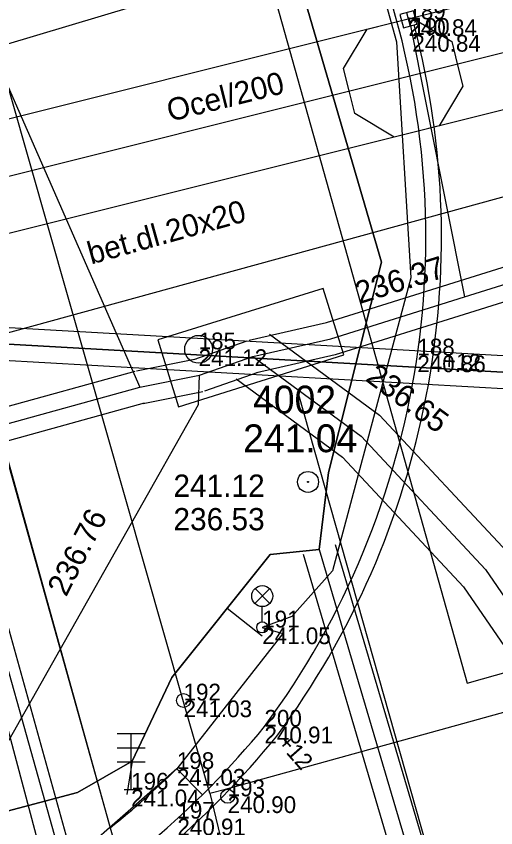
# Model space of a CAD drawing. Extents: x -599432 to -598680, y -1159407 to -1158632.
# Drawn here: x -599037.98 to -599029.38, y -1158897.84 to -1158883.28 of the extents above; entities that cross this region are included whole.
import ezdxf

# ---------------------------------------------------------------- set-up
doc = ezdxf.new("R2010")
doc.units = 0
for name, color, linetype in [('0001 VY - Body PBP', 7, 'Continuous'), ('0002 VY - Body PBP - čísla', 7, 'Continuous'), ('0003 VY - Body PBP - výšky', 7, 'Continuous'), ('0004 VY - Body podrobné', 7, 'Continuous'), ('0005 VY - Body podrobné - čísla', 7, 'Continuous'), ('0006 VY - Body podrobné - výšky', 7, 'Continuous'), ('0027 ZA - Silnice_cesta zpevněná', 7, 'Continuous'), ('0031 ZA - Ostatní rozhraní', 7, 'Continuous'), ('0032 TE - Popis povrchu', 7, 'Continuous'), ('0057 ZA - Doprava - BKOM buňky', 7, 'Continuous'), ('0073 TE - Výška obrubníků a zdí', 7, 'Continuous'), ('0075 ZA - BVK - kanalizace - buňky', 7, 'Continuous'), ('0080 ZA - BVK - vodovod - buňky', 7, 'Continuous'), ('0105 ZA - TSB - VO - buňky', 7, 'Continuous'), ('0201 PV - BVK - kanalizace - popis', 7, 'Continuous'), ('0203 PV - BVK - kanalizace - dešťová přípojka', 7, 'Continuous'), ('0206 PV - BVK - kanalizace - jednotná', 7, 'Continuous'), ('0209 PV - BVK - kanalizace - obvod šachty', 7, 'Continuous'), ('0211 PV - BVK - kanalizace - jednotná okraj', 7, 'Continuous'), ('0214 PV - BVK - vodovod - pitná', 7, 'Continuous'), ('0264 PV - TB - parovod mimo provoz', 7, 'Continuous'), ('0301 PV - RWE - popis', 7, 'Continuous'), ('0302 PV - RWE - NTL', 7, 'Continuous'), ('0308 PV - RWE - ochranné pásmo', 7, 'Continuous'), ('0359 PV - EON - sdělovací kabely', 7, 'Continuous'), ('0368 PV - EON - sdělovací chránička', 7, 'Continuous'), ('0407 PV - TSB - kabelové vedení přibližný zákres', 7, 'Continuous'), ('0454 PV - O2 - kabel zaměřený', 7, 'Continuous'), ('0455 PV - O2 - kabel nezaměřený', 7, 'Continuous'), ('0530 PV - T-mobile - optické kabely', 7, 'Continuous'), ('0652 PV - BKOM - kabely bez rozlišení', 7, 'Continuous'), ('0653 PV - BKOM - chranička', 7, 'Continuous'), ('0703 PV - DIAL TELECOM optický kabel', 7, 'Continuous')]:
    doc.layers.add(name, color=color, linetype=linetype)

msp = doc.modelspace()

# ---------------------------------------------------------------- linework, layer by layer
at = {"layer": '0001 VY - Body PBP'}
for radius in [0.188, 0.00896]:
    msp.add_circle((-599032.75, -1158891.64), radius, dxfattribs=at)
at = {"layer": '0004 VY - Body podrobné'}
for p, q in [((-599030.95, -1158883.34), (-599030.95, -1158883.34)), ((-599030.88, -1158883.62), (-599030.88, -1158883.62)), ((-599034.71, -1158889.26), (-599034.71, -1158889.26)), ((-599030.79, -1158889.37), (-599030.79, -1158889.37)), ((-599033.57, -1158894.25), (-599033.57, -1158894.25)), ((-599034.98, -1158895.56), (-599034.98, -1158895.56)), ((-599033.53, -1158896.03), (-599033.53, -1158896.03)), ((-599035.1, -1158896.79), (-599035.1, -1158896.79)), ((-599035.92, -1158897.16), (-599035.92, -1158897.16)), ((-599034.19, -1158897.28), (-599034.19, -1158897.28)), ((-599035.09, -1158897.68), (-599035.09, -1158897.68))]:
    msp.add_line(p, q, dxfattribs=at)
at = {"layer": '0027 ZA - Silnice_cesta zpevněná'}
for centre, radius, start, end in [((-599045.404, -1158887.251), 14.766, 323.5232, 19.0984), ((-599045.614, -1158886.167), 15.598, 299.5987, 320.7801)]:
    msp.add_arc(centre, radius, start, end, dxfattribs=at)
at = {"layer": '0031 ZA - Ostatní rozhraní'}
for p, q in [((-599041.68, -1158878.521), (-599036.294, -1158897.844)), ((-599041.14, -1158883.437), (-599036.98, -1158898.36)), ((-599034.641, -1158897.253), (-599035.104, -1158896.786))]:
    msp.add_line(p, q, dxfattribs=at)
for centre, radius, start, end in [((-599045.404, -1158887.251), 15.046, 323.4977, 14.6672), ((-599045.614, -1158886.167), 15.878, 299.5786, 320.8043), ((-599045.614, -1158886.167), 14.94, 308.5987, 314.7062)]:
    msp.add_arc(centre, radius, start, end, dxfattribs=at)
at = {"layer": '0057 ZA - Doprava - BKOM buňky'}
for p, q in [((-599035.67, -1158896.16), (-599036.17, -1158896.16)), ((-599035.92, -1158897.16), (-599035.92, -1158896.16)), ((-599036.17, -1158896.41), (-599035.67, -1158896.41)), ((-599036.17, -1158896.66), (-599035.67, -1158896.66)), ((-599036.045, -1158897.16), (-599035.795, -1158897.16))]:
    msp.add_line(p, q, dxfattribs=at)
at = {"layer": '0075 ZA - BVK - kanalizace - buňky'}
msp.add_line((-599030.983, -1158883.219), (-599030.917, -1158883.461), dxfattribs=at)
msp.add_lwpolyline([(-599031.103, -1158883.252), (-599031.038, -1158883.493), (-599030.797, -1158883.428), (-599030.862, -1158883.187)], close=True, dxfattribs=at)
msp.add_circle((-599034.71, -1158889.26), 0.25, dxfattribs=at)
at = {"layer": '0080 ZA - BVK - vodovod - buňky'}
for centre in [(-599034.98, -1158895.56), (-599034.19, -1158897.28)]:
    msp.add_circle(centre, 0.125, dxfattribs=at)
at = {"layer": '0105 ZA - TSB - VO - buňky'}
for p, q in [((-599033.434, -1158893.818), (-599033.698, -1158893.553)), ((-599033.702, -1158893.819), (-599033.438, -1158893.555)), ((-599033.57, -1158894.15), (-599033.57, -1158893.875))]:
    msp.add_line(p, q, dxfattribs=at)
for centre, radius in [((-599033.57, -1158893.688), 0.188), ((-599033.57, -1158894.25), 0.1)]:
    msp.add_circle(centre, radius, dxfattribs=at)
at = {"layer": '0203 PV - BVK - kanalizace - dešťová přípojka'}
msp.add_line((-599030.942, -1158883.305), (-599029.946, -1158888.32), dxfattribs=at)
msp.add_line((-599030.942, -1158883.305), (-599029.946, -1158888.32), dxfattribs=at)
at = {"layer": '0206 PV - BVK - kanalizace - jednotná'}
for p, q in [((-599041.22, -1158877.49), (-599035.766, -1158889.94)), ((-599041.22, -1158877.49), (-599035.766, -1158889.94)), ((-599034.697, -1158889.724), (-599033.74, -1158889.39)), ((-599035.766, -1158889.94), (-599034.697, -1158889.724)), ((-599034.71, -1158890.253), (-599034.697, -1158889.724)), ((-599034.71, -1158890.253), (-599034.697, -1158889.724)), ((-599091.321, -1158905.303), (-599035.766, -1158889.94)), ((-599055.379, -1158926.835), (-599034.71, -1158890.253)), ((-599055.379, -1158926.835), (-599034.71, -1158890.253))]:
    msp.add_line(p, q, dxfattribs=at)
for points in [[(-599033.74, -1158889.39), (-599032.341, -1158889.07), (-599029.946, -1158888.32), (-599018.079, -1158884.603)], [(-599033.74, -1158889.39), (-599031.8, -1158890.82), (-599029.57, -1158893.21), (-599027.06, -1158896.87), (-599025.46, -1158900.47), (-599024.64, -1158903.44), (-599009.567, -1158957.636)]]:
    msp.add_lwpolyline(points, dxfattribs=at)
at = {"layer": '0209 PV - BVK - kanalizace - obvod šachty'}
msp.add_lwpolyline([(-599035.44, -1158889.09), (-599035.07, -1158890.29), (-599032.11, -1158889.36), (-599032.48, -1158888.17)], close=True, dxfattribs=at)
at = {"layer": '0211 PV - BVK - kanalizace - jednotná okraj'}
for p, q in [((-599034.796, -1158889.441), (-599033.839, -1158889.107)), ((-599035.825, -1158889.646), (-599034.756, -1158889.43)), ((-599091.401, -1158905.014), (-599035.846, -1158889.651)), ((-599034.598, -1158890.007), (-599033.641, -1158889.673)), ((-599035.707, -1158890.234), (-599034.638, -1158890.018)), ((-599035.686, -1158890.229), (-599091.242, -1158905.592))]:
    msp.add_line(p, q, dxfattribs=at)
for points in [[(-599033.807, -1158889.098), (-599032.419, -1158888.78), (-599030.036, -1158888.034), (-599018.169, -1158884.317)], [(-599017.989, -1158884.889), (-599029.856, -1158888.606), (-599032.263, -1158889.36), (-599033.673, -1158889.682)], [(-599033.443, -1158888.988), (-599031.466, -1158890.445), (-599029.179, -1158892.896), (-599026.622, -1158896.625), (-599024.988, -1158900.301), (-599024.158, -1158903.306), (-599009.085, -1158957.502)], [(-599034.037, -1158889.792), (-599032.134, -1158891.195), (-599029.961, -1158893.524), (-599027.498, -1158897.115), (-599025.932, -1158900.639), (-599025.122, -1158903.574), (-599010.049, -1158957.77)]]:
    msp.add_lwpolyline(points, dxfattribs=at)
at = {"layer": '0214 PV - BVK - vodovod - pitná'}
for q in [(-599034.98, -1158895.587), (-599034.23, -1158897.15)]:
    msp.add_line((-599034.512, -1158897.222), q, dxfattribs=at)
for points in [[(-599034.98, -1158895.587), (-599043.597, -1158865.343), (-599050.485, -1158841.158), (-599054.704, -1158825.464)], [(-599034.23, -1158897.15), (-599025.055, -1158894.612), (-599019.244, -1158893.004), (-599016.56, -1158892.26), (-599016.08, -1158892.128)], [(-599034.512, -1158897.222), (-599034.25, -1158898.295), (-599033.898, -1158899.704)]]:
    msp.add_lwpolyline(points, dxfattribs=at)
at = {"layer": '0264 PV - TB - parovod mimo provoz'}
for p, q in [((-599015.807, -1158882.836), (-599046.634, -1158891.306)), ((-599017.96, -1158942.926), (-599032.913, -1158890.076))]:
    msp.add_line(p, q, dxfattribs=at)
at = {"layer": '0302 PV - RWE - NTL'}
for points in [[(-599031.044, -1158884.383), (-598999.16, -1158876.4), (-598995.29, -1158875.42), (-598995.15, -1158875.39), (-598995.04, -1158875.36)], [(-599039.1, -1158886.4), (-599031.044, -1158884.383)], [(-599039.81, -1158889.02), (-599019.564, -1158961.355)]]:
    msp.add_lwpolyline(points, dxfattribs=at)
at = {"layer": '0308 PV - RWE - ochranné pásmo'}
for points in [[(-599031.689, -1158883.514), (-599031.287, -1158883.413), (-598999.404, -1158875.43), (-598995.518, -1158874.446), (-598995.387, -1158874.418), (-598995.303, -1158874.395), (-598994.903, -1158874.286), (-598994.184, -1158874.697), (-598994.075, -1158875.097), (-598993.966, -1158875.497), (-598994.377, -1158876.216), (-598994.777, -1158876.325), (-598994.913, -1158876.362), (-598995.062, -1158876.394), (-598998.916, -1158877.37), (-599030.801, -1158885.353), (-599031.203, -1158885.454), (-599031.913, -1158885.028), (-599032.014, -1158884.626), (-599032.115, -1158884.224)], [(-599039.745, -1158885.531), (-599039.343, -1158885.43), (-599031.287, -1158883.413), (-599030.885, -1158883.312), (-599030.175, -1158883.738), (-599030.074, -1158884.14), (-599029.973, -1158884.542), (-599030.399, -1158885.252), (-599030.801, -1158885.353), (-599038.857, -1158887.37), (-599039.259, -1158887.471), (-599039.969, -1158887.045), (-599040.07, -1158886.643), (-599040.171, -1158886.241)], [(-599018.602, -1158961.079), (-599020.526, -1158961.63), (-599040.773, -1158889.29), (-599040.885, -1158888.891), (-599040.479, -1158888.169), (-599040.08, -1158888.057), (-599039.681, -1158887.945), (-599038.959, -1158888.351), (-599038.847, -1158888.75)]]:
    msp.add_lwpolyline(points, close=True, dxfattribs=at)
at = {"layer": '0359 PV - EON - sdělovací kabely'}
msp.add_lwpolyline([(-599153, -1158925.67), (-599136.91, -1158920.86), (-599119.51, -1158916.31), (-599104.33, -1158911.91), (-599088.3, -1158908.08), (-599074.72, -1158903.34), (-599063.86, -1158900.66), (-599061.95, -1158898.88), (-599061.24, -1158895.32), (-599061.55, -1158893.87), (-599062.09, -1158890.79), (-599061.3, -1158889.79), (-599054.31, -1158887.73), (-599051.84, -1158888.39), (-598992.76, -1158891.74), (-598991.64, -1158891.24), (-598990.73, -1158890.27)], dxfattribs=at)
msp.add_lwpolyline([(-599153, -1158925.67), (-599136.91, -1158920.86), (-599119.51, -1158916.31), (-599104.33, -1158911.91), (-599088.3, -1158908.08), (-599074.72, -1158903.34), (-599063.86, -1158900.66), (-599061.95, -1158898.88), (-599061.24, -1158895.32), (-599061.55, -1158893.87), (-599062.09, -1158890.79), (-599061.3, -1158889.79), (-599054.31, -1158887.73), (-599051.84, -1158888.39), (-598992.76, -1158891.74), (-598991.64, -1158891.24), (-598990.73, -1158890.27)], dxfattribs=at)
at = {"layer": '0368 PV - EON - sdělovací chránička'}
for p, q in [((-599051.823, -1158888.09), (-598992.743, -1158891.44)), ((-598992.777, -1158892.04), (-599051.857, -1158888.69))]:
    msp.add_line(p, q, dxfattribs=at)
at = {"layer": '0407 PV - TSB - kabelové vedení přibližný zákres'}
for p, q in [((-599034.231, -1158872.76), (-599031.163, -1158883.745)), ((-599031.163, -1158883.745), (-599030.908, -1158887.981)), ((-599030.908, -1158887.981), (-599032.311, -1158893.237)), ((-599032.311, -1158893.237), (-599033.038, -1158894.054)), ((-599033.038, -1158894.054), (-599033.57, -1158894.25)), ((-599033.57, -1158894.25), (-599033.204, -1158894.36)), ((-599033.204, -1158894.36), (-599035.104, -1158896.786)), ((-599035.104, -1158896.786), (-599037.938, -1158899.272))]:
    msp.add_line(p, q, dxfattribs=at)
at = {"layer": '0454 PV - O2 - kabel zaměřený'}
msp.add_lwpolyline([(-599033.5, -1158882.39), (-599029.9, -1158895.25), (-599027.59, -1158894.6), (-599014.08, -1158890.98), (-599009.96, -1158889.87)], dxfattribs=at)
at = {"layer": '0455 PV - O2 - kabel nezaměřený'}
msp.add_lwpolyline([(-599033.5, -1158882.39), (-599041.16, -1158884.69), (-599029.5, -1158928.59)], dxfattribs=at)
at = {"layer": '0530 PV - T-mobile - optické kabely'}
msp.add_lwpolyline([(-598992.76, -1158891.739), (-599051.839, -1158888.389)], dxfattribs=at)
at = {"layer": '0652 PV - BKOM - kabely bez rozlišení'}
for p, q in [((-599034.196, -1158893.902), (-599033.57, -1158894.4)), ((-599035.9, -1158896.65), (-599036, -1158897.25))]:
    msp.add_line(p, q, dxfattribs=at)
for points in [[(-599069.54, -1158906.27), (-599056.01, -1158902.46), (-599042.94, -1158898.82), (-599036.88, -1158897.21), (-599035.9, -1158896.65), (-599035.19, -1158895.15), (-599033.43, -1158892.94), (-599032.55, -1158892.85), (-599032.38, -1158891.47), (-599031.43, -1158887.7), (-599033.39, -1158880.98), (-599034.34, -1158877.53), (-599034.11, -1158876.42), (-599020.38, -1158872.59), (-599019.95, -1158872.38), (-599019.48, -1158873.04), (-599018.91, -1158874.17), (-599016.73, -1158875.93), (-599015.62, -1158876.75), (-599013.57, -1158877.37), (-599011.16, -1158877.03), (-599007.55, -1158875.71), (-599006.793, -1158874.464)], [(-599034.11, -1158876.42), (-599034.34, -1158877.53), (-599033.39, -1158880.98), (-599031.43, -1158887.7), (-599032.38, -1158891.47), (-599032.55, -1158892.85), (-599033.43, -1158892.94), (-599035.19, -1158895.15), (-599035.9, -1158896.65), (-599036.88, -1158897.21), (-599042.94, -1158898.82), (-599056.01, -1158902.46), (-599055.88, -1158902.71)], [(-599032.55, -1158892.85), (-599025.77, -1158915.82), (-599025.82, -1158914.68), (-599026.87, -1158913.05), (-599029.47, -1158911.41), (-599032.14, -1158911.02), (-599033.01, -1158911.65), (-599035.81, -1158912.5), (-599040.07, -1158913.21)]]:
    msp.add_lwpolyline(points, dxfattribs=at)
at = {"layer": '0653 PV - BKOM - chranička'}
for p, q in [((-599032.262, -1158892.765), (-599025.482, -1158915.735)), ((-599032.838, -1158892.935), (-599026.058, -1158915.905))]:
    msp.add_line(p, q, dxfattribs=at)
at = {"layer": '0703 PV - DIAL TELECOM optický kabel'}
for points in [[(-598991.64, -1158891.24), (-598992.76, -1158891.74), (-599051.84, -1158888.39), (-599054.31, -1158887.73), (-599061.3, -1158889.79), (-599062.09, -1158890.79), (-599061.55, -1158893.87)], [(-598992.76, -1158891.74), (-599051.84, -1158888.39)]]:
    msp.add_lwpolyline(points, dxfattribs=at)

# ---------------------------------------------------------------- texts
at = {"layer": '0002 VY - Body PBP - čísla'}
msp.add_text('4002', height=0.5, dxfattribs=at).set_placement((-599033.734, -1158890.413))
at = {"layer": '0003 VY - Body PBP - výšky'}
msp.add_text('241.04', height=0.5, dxfattribs=at).set_placement((-599033.912, -1158891.107))
at = {"layer": '0005 VY - Body podrobné - čísla'}
for s, p in [('189', (-599030.95, -1158883.34)), ('190', (-599030.88, -1158883.62)), ('185', (-599034.71, -1158889.26)), ('188', (-599030.79, -1158889.37)), ('191', (-599033.57, -1158894.25)), ('192', (-599034.98, -1158895.56)), ('200', (-599033.53, -1158896.03)), ('198', (-599035.1, -1158896.79)), ('196', (-599035.92, -1158897.16)), ('193', (-599034.19, -1158897.28)), ('197', (-599035.09, -1158897.68))]:
    msp.add_text(s, height=0.3, dxfattribs=at).set_placement(p)
at = {"layer": '0006 VY - Body podrobné - výšky'}
for s, p in [('240.84', (-599030.95, -1158883.64)), ('240.84', (-599030.88, -1158883.92)), ('241.12', (-599034.71, -1158889.56)), ('240.86', (-599030.79, -1158889.67)), ('241.05', (-599033.57, -1158894.55)), ('241.03', (-599034.98, -1158895.86)), ('240.91', (-599033.53, -1158896.33)), ('241.03', (-599035.1, -1158897.09)), ('241.04', (-599035.92, -1158897.46)), ('240.90', (-599034.19, -1158897.58)), ('240.91', (-599035.09, -1158897.98))]:
    msp.add_text(s, height=0.3, dxfattribs=at).set_placement(p)
at = {"layer": '0032 TE - Popis povrchu'}
msp.add_text('bet.dl.20x20', height=0.4, rotation=15.576, dxfattribs=at).set_placement((-599036.638, -1158887.74))
at = {"layer": '0073 TE - Výška obrubníků a zdí'}
for rotation, p in [(356.7546, (-599030.341, -1158889.612)), (311.3802, (-599033.312, -1158896.322))]:
    msp.add_text('+12', height=0.3, rotation=rotation, dxfattribs=at).set_placement(p)
at = {"layer": '0201 PV - BVK - kanalizace - popis'}
for s, rotation, p in [('236.37', 17.3917, (-599031.826, -1158888.45)), ('236.65', 323.6066, (-599031.741, -1158889.812)), ('236.76', 62.8535, (-599037.085, -1158893.714)), ('236.76', 62.8535, (-599037.085, -1158893.714))]:
    msp.add_text(s, height=0.4, rotation=rotation, dxfattribs=at).set_placement(p)
for s, p in [('241.12', (-599035.162, -1158891.908)), ('236.53', (-599035.162, -1158892.508))]:
    msp.add_text(s, height=0.4, dxfattribs=at).set_placement(p)
at = {"layer": '0301 PV - RWE - popis'}
msp.add_text('Ocel/200', height=0.4, rotation=14.0563, dxfattribs=at).set_placement((-599035.223, -1158885.179))

doc.saveas('drawing.dxf')
